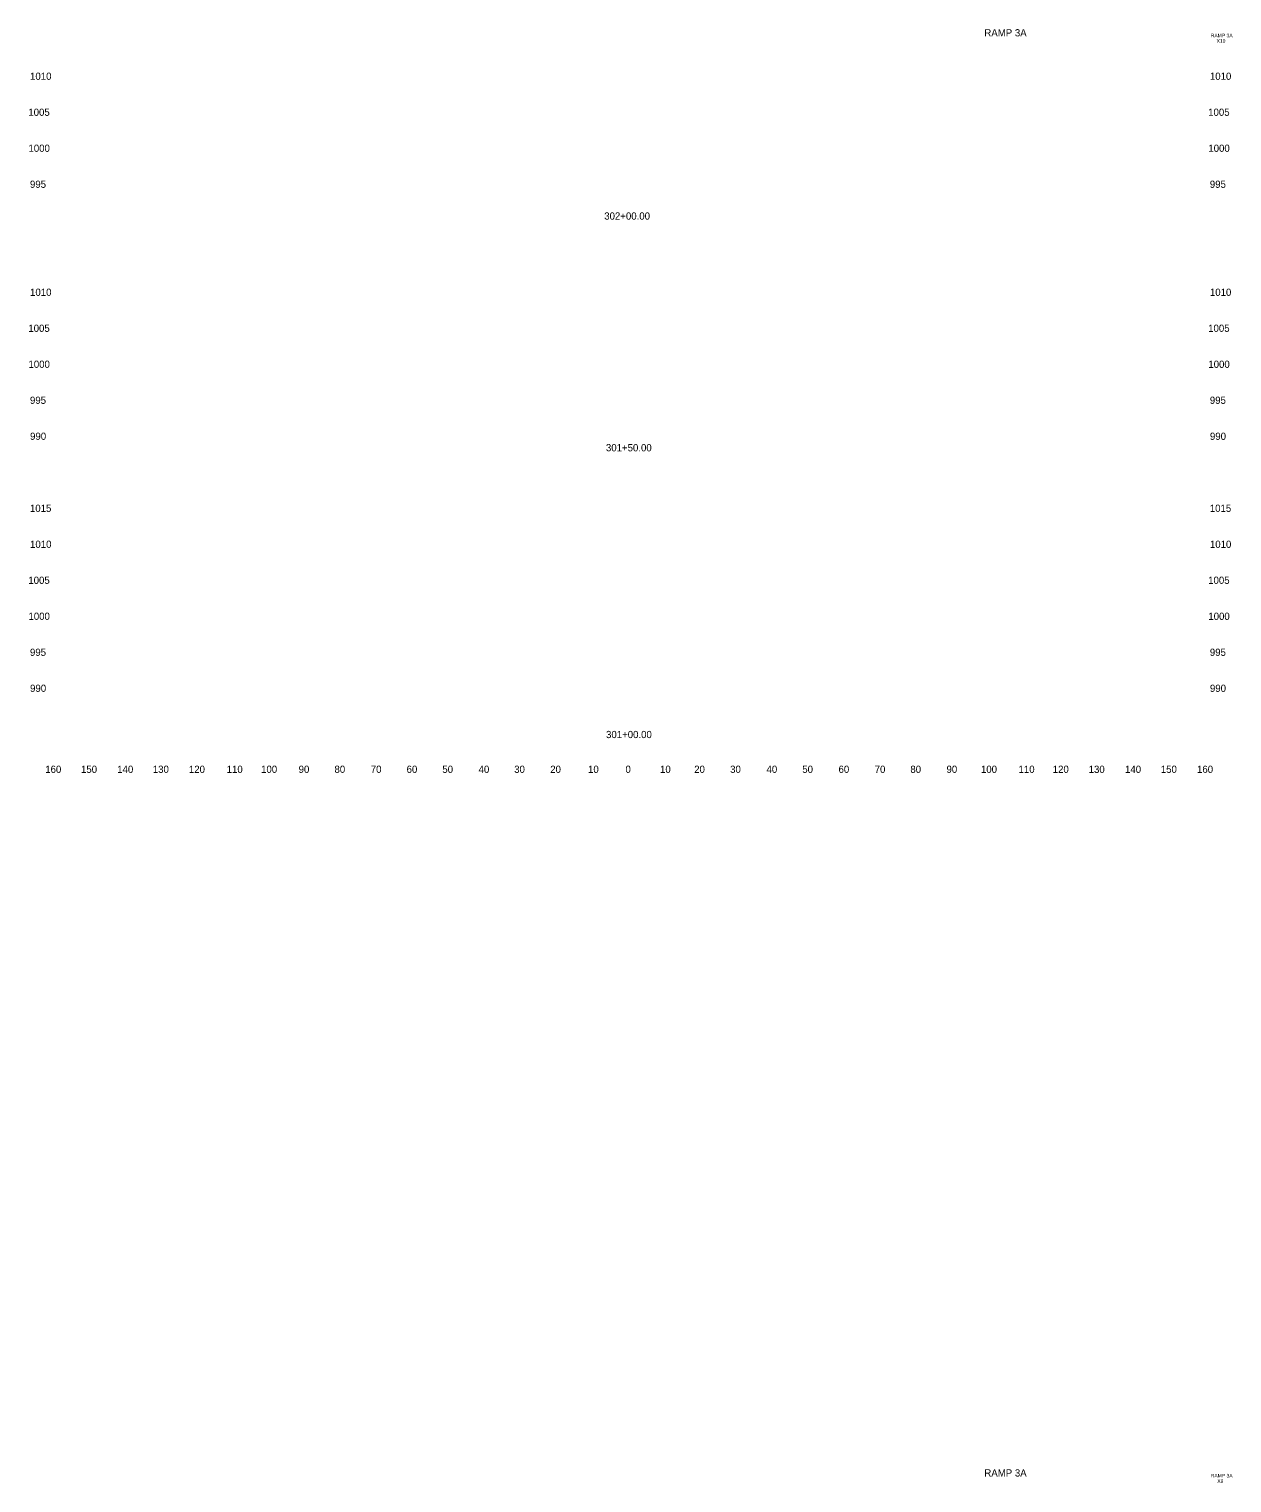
# Model space of a CAD drawing. Extents: x 4286 to 5843, y 4997 to 8804.
# Drawn here: x 4993.6 to 5327.8, y 8400.3 to 8804.1 of the extents above; entities that cross this region are included whole.
import ezdxf

# ---------------------------------------------------------------- set-up
doc = ezdxf.new("R2010")
doc.units = 0
for name, color, linetype in [('RD_SHT_ID', 7, 'Continuous'), ('RD_XS_TX_Offset', 7, 'Continuous'), ('RD_XS_TX_Station', 7, 'Continuous')]:
    doc.layers.add(name, color=color, linetype=linetype)

msp = doc.modelspace()

# ---------------------------------------------------------------- texts
at = {"layer": 'RD_SHT_ID'}
for s, height, p in [('RAMP 3A', 2, (5259.02, 8802.06)), ('RAMP 3A', 1, (5321.93, 8801.8)), ('X10', 1, (5323.53, 8800.3)), ('RAMP 3A', 2, (5259.02, 8402.06)), ('RAMP 3A', 1, (5321.93, 8401.8)), ('X9', 1, (5323.74, 8400.3))]:
    msp.add_text(s, height=height, dxfattribs=at).set_placement(p)
at = {"layer": 'RD_XS_TX_Offset'}
for s, p in [('1010', (4993.88, 8790)), ('1010', (5321.68, 8790)), ('1005', (4993.4, 8780)), ('1005', (5321.2, 8780)), ('1000', (4993.44, 8770)), ('1000', (5321.24, 8770)), ('995', (4993.86, 8760)), ('995', (5321.66, 8760)), ('1010', (4993.88, 8730)), ('1010', (5321.68, 8730)), ('1005', (4993.4, 8720)), ('1005', (5321.2, 8720)), ('1000', (4993.44, 8710)), ('1000', (5321.24, 8710)), ('995', (4993.86, 8700)), ('995', (5321.66, 8700)), ('990', (4993.89, 8690)), ('990', (5321.69, 8690)), ('1015', (4993.85, 8670)), ('1015', (5321.65, 8670)), ('1010', (4993.88, 8660)), ('1010', (5321.68, 8660)), ('1005', (4993.4, 8650)), ('1005', (5321.2, 8650)), ('1000', (4993.44, 8640)), ('1000', (5321.24, 8640)), ('995', (4993.86, 8630)), ('995', (5321.66, 8630)), ('990', (4993.89, 8620)), ('990', (5321.69, 8620)), ('160', (4998.1, 8597.5)), ('150', (5008.04, 8597.5)), ('140', (5018.1, 8597.5)), ('130', (5027.99, 8597.5)), ('120', (5038.01, 8597.5)), ('110', (5048.51, 8597.5)), ('100', (5058.07, 8597.5)), ('90', (5068.5, 8597.5)), ('80', (5078.46, 8597.5)), ('70', (5088.54, 8597.5)), ('60', (5098.5, 8597.5)), ('50', (5108.43, 8597.5)), ('40', (5118.5, 8597.5)), ('30', (5128.39, 8597.5)), ('20', (5138.4, 8597.5)), ('10', (5148.91, 8597.5)), ('0', (5159.3, 8597.5)), ('0', (5159.3, 8597.5)), ('10', (5168.91, 8597.5)), ('20', (5178.4, 8597.5)), ('30', (5188.39, 8597.5)), ('40', (5198.5, 8597.5)), ('50', (5208.43, 8597.5)), ('60', (5218.5, 8597.5)), ('70', (5228.54, 8597.5)), ('80', (5238.46, 8597.5)), ('90', (5248.5, 8597.5)), ('100', (5258.07, 8597.5)), ('110', (5268.51, 8597.5)), ('120', (5278.01, 8597.5)), ('130', (5287.99, 8597.5)), ('140', (5298.1, 8597.5)), ('150', (5308.04, 8597.5)), ('160', (5318.1, 8597.5))]:
    msp.add_text(s, height=2, dxfattribs=at).set_placement(p)
at = {"layer": 'RD_XS_TX_Station'}
for s, p in [('302+00.00', (5153.41, 8751.17)), ('301+50.00', (5153.88, 8686.82)), ('301+00.00', (5153.91, 8607.16))]:
    msp.add_text(s, height=2, dxfattribs=at).set_placement(p)

doc.saveas('drawing.dxf')
